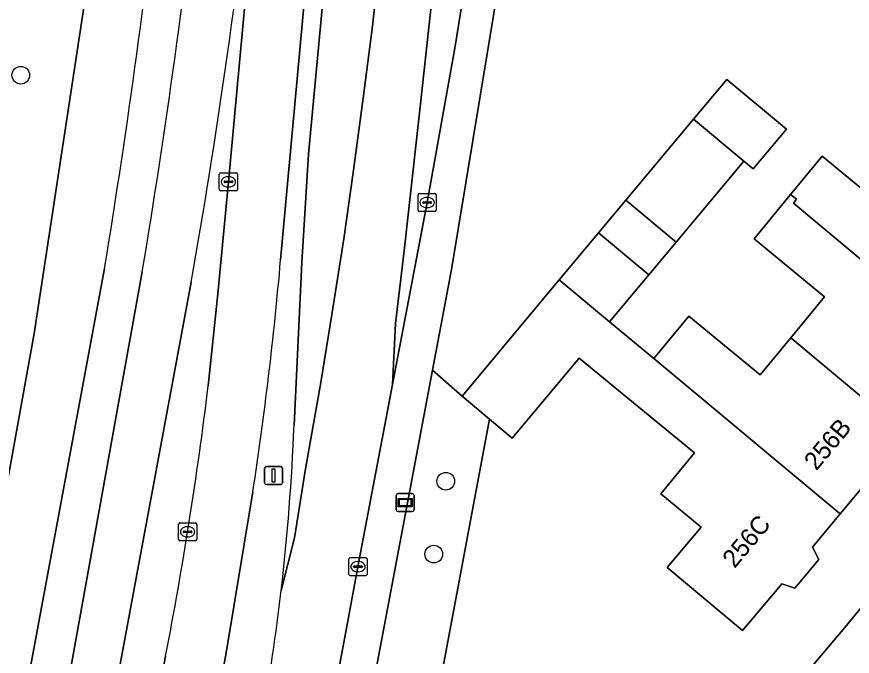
# Model space of a CAD drawing. Extents: x 160157 to 160921, y 381516 to 382045.
# Drawn here: x 160513.39 to 160559.64, y 381764.83 to 381800.21 of the extents above; entities that cross this region are included whole.
import ezdxf

# ---------------------------------------------------------------- set-up
doc = ezdxf.new("R2010")
doc.units = 0
for name, color, linetype in [('IMGEO_Berm_gesloten', 7, 'Continuous'), ('IMGEO_Berm_groen', 7, 'Continuous'), ('IMGEO_Boom', 7, 'Continuous'), ('IMGEO_Erf', 7, 'Continuous'), ('IMGEO_Groenvoorziening', 7, 'Continuous'), ('IMGEO_Kolk', 7, 'Continuous'), ('IMGEO_Lichtmast', 7, 'Continuous'), ('IMGEO_Muur', 7, 'Continuous'), ('IMGEO_Pand', 7, 'Continuous'), ('IMGEO_Pand_nummerreeks', 7, 'Continuous'), ('IMGEO_Rijbaan_regionaal_gesloten', 7, 'Continuous'), ('IMGEO_Voetpad_open', 7, 'Continuous'), ('IMGEO_Wegwijzer', 7, 'Continuous')]:
    doc.layers.add(name, color=color, linetype=linetype)

msp = doc.modelspace()

# ---------------------------------------------------------------- linework, layer by layer
at = {"layer": 'IMGEO_Berm_gesloten'}
for points in [[(160537.367, 381907.526), (160535.336, 381877.881), (160533.178, 381846.489), (160532.157, 381832.058), (160528.001, 381786.763)], [(160528.742, 381777.62), (160529.18, 381786.609), (160529.545, 381792.616), (160532.528, 381824.512), (160533.226, 381832.551), (160534.083, 381843.54), (160536.45, 381877.717), (160538.181, 381902.406)], [(160526.466, 381773.924), (160524.967, 381764.913), (160522.088, 381750), (160521.362, 381746.238)]]:
    msp.add_lwpolyline(points, dxfattribs=at)
for centre, radius, start, end in [((160328.232, 381804.136), 200.523, 351.33458, 355.02985), ((160410.748, 381782.193), 118.083, 353.32437, 357.78058), ((160412.245, 381781.977), 116.571, 350.98273, 353.34405)]:
    msp.add_arc(centre, radius, start, end, dxfattribs=at)
at = {"layer": 'IMGEO_Berm_groen'}
for points in [[(160534.614, 381926.093), (160532.965, 381928.317), (160530.336, 381929.12), (160526.984, 381926.458), (160523.346, 381875.055), (160520.714, 381837.873), (160520.28, 381829.952), (160520.063, 381825.981), (160517.843, 381805.586), (160514.368, 381782.689), (160510.053, 381758.978), (160509.927, 381757.953), (160509.344, 381753.204), (160510.68, 381750.562), (160513.728, 381750), (160514.409, 381749.874), (160514.559, 381750), (160516.8, 381751.896), (160523.052, 381785.526)], [(160523.992, 381779.798), (160524.523, 381784.877), (160525.11, 381791.078), (160526.59, 381807.082), (160527.114, 381812.495), (160528.774, 381830.898), (160530.173, 381850.327), (160531.52, 381869.788), (160533, 381891.221)], [(160505.903, 381781.897), (160505.796, 381779.917), (160504.746, 381758.207), (160509.927, 381757.953), (160510.053, 381758.978), (160514.368, 381782.689), (160517.843, 381805.586)], [(160520.343, 381786.102), (160514.475, 381753.541), (160513.2, 381753.054), (160512.205, 381753.816), (160518.254, 381786.275)], [(160518.254, 381786.275), (160512.205, 381753.816), (160513.2, 381753.054), (160514.475, 381753.541), (160520.343, 381786.102)], [(160523.052, 381785.526), (160516.8, 381751.896), (160514.559, 381750), (160514.409, 381749.874), (160518.635, 381749.141), (160518.807, 381750), (160519.13, 381751.61), (160521.633, 381764.829)]]:
    msp.add_lwpolyline(points, dxfattribs=at)
for centre, radius, start, end in [((160092.55, 381856.358), 431.434, 350.65138, 357.02816), ((160092.55, 381856.358), 431.434, 350.65138, 357.02816), ((160083.837, 381858.802), 442.519, 350.5442, 356.78225), ((160083.837, 381858.802), 442.519, 350.5442, 356.78225), ((160153.748, 381850.796), 375.027, 349.97715, 357.39851), ((160153.748, 381850.796), 375.027, 349.97715, 357.39851), ((160314.708, 381805.109), 210.809, 348.98452, 353.10404)]:
    msp.add_arc(centre, radius, start, end, dxfattribs=at)
at = {"layer": 'IMGEO_Boom'}
for centre in [(160513.621, 381796.978), (160537.142, 381774.514), (160536.478, 381770.482)]:
    msp.add_circle(centre, 0.489, dxfattribs=at)
at = {"layer": 'IMGEO_Erf'}
for points in [[(160540.802, 381806.439), (160539.434, 381798.152), (160537.466, 381786.23), (160536.414, 381780.659), (160538.044, 381779.218), (160543.426, 381785.657), (160545.598, 381788.256), (160547.107, 381790.062), (160550.859, 381794.551), (160552.693, 381796.747), (160555.991, 381793.99), (160554.156, 381791.795), (160553.637, 381792.229), (160549.884, 381787.74), (160548.375, 381785.935), (160546.207, 381783.342), (160548.665, 381781.296), (160550.599, 381783.648), (160554.551, 381780.398), (160556.234, 381782.446), (160558.103, 381784.719), (160554.204, 381787.925), (160556.228, 381790.387), (160557.966, 381792.501), (160561.933, 381789.24)], [(160562.638, 381777.096), (160558.979, 381772.71), (160557.434, 381770.858), (160557.796, 381770.185), (160556.453, 381768.597), (160555.742, 381768.829), (160555.484, 381768.52), (160553.562, 381766.248), (160549.402, 381769.734), (160551.278, 381771.979), (160549.047, 381773.813), (160550.909, 381776.077), (160547.01, 381779.283), (160544.524, 381781.328), (160540.815, 381776.891), (160539.559, 381777.945), (160536.769, 381763.076)], [(160556.812, 381763.555), (160559.232, 381766.417), (160566.256, 381774.976)]]:
    msp.add_lwpolyline(points, dxfattribs=at)
at = {"layer": 'IMGEO_Groenvoorziening'}
msp.add_lwpolyline([(160537.22, 381749.558), (160534.647, 381751.702), (160535.455, 381756.063), (160536.769, 381763.076), (160539.559, 381777.945), (160538.044, 381779.218), (160536.414, 381780.659), (160535.155, 381773.997), (160533.001, 381762.573), (160531.549, 381754.827), (160530.76, 381750.659), (160530.838, 381750)], dxfattribs=at)
at = {"layer": 'IMGEO_Kolk'}
for p, q in [((160524.608, 381790.652), (160524.608, 381791.504)), ((160524.683, 381791.578), (160525.535, 381791.578)), ((160525.609, 381791.504), (160525.609, 381790.652)), ((160524.867, 381791.072), (160524.867, 381791.084)), ((160525.305, 381791.035), (160524.907, 381791.035)), ((160524.91, 381791.121), (160525.308, 381791.121)), ((160525.096, 381791.358), (160525.121, 381791.358)), ((160525.351, 381791.084), (160525.351, 381791.072)), ((160525.535, 381790.578), (160524.683, 381790.578)), ((160525.119, 381790.798), (160525.094, 381790.798)), ((160535.608, 381789.509), (160535.608, 381790.361)), ((160535.683, 381790.435), (160536.535, 381790.435)), ((160536.096, 381790.215), (160536.121, 381790.215)), ((160536.609, 381790.361), (160536.609, 381789.509)), ((160535.867, 381789.929), (160535.867, 381789.941)), ((160536.305, 381789.892), (160535.907, 381789.892)), ((160535.91, 381789.978), (160536.308, 381789.978)), ((160536.119, 381789.655), (160536.094, 381789.655)), ((160536.351, 381789.941), (160536.351, 381789.929)), ((160536.535, 381789.435), (160535.683, 381789.435)), ((160522.353, 381771.29), (160522.353, 381772.142)), ((160522.428, 381772.216), (160523.28, 381772.216)), ((160522.841, 381771.996), (160522.866, 381771.996)), ((160523.354, 381772.142), (160523.354, 381771.29)), ((160522.612, 381771.71), (160522.612, 381771.722)), ((160523.05, 381771.673), (160522.652, 381771.673)), ((160522.655, 381771.759), (160523.053, 381771.759)), ((160523.096, 381771.722), (160523.096, 381771.71)), ((160523.28, 381771.216), (160522.428, 381771.216)), ((160522.864, 381771.436), (160522.839, 381771.436)), ((160531.782, 381769.361), (160531.782, 381770.213)), ((160531.857, 381770.287), (160532.709, 381770.287)), ((160532.783, 381770.213), (160532.783, 381769.361)), ((160532.041, 381769.781), (160532.041, 381769.793)), ((160532.479, 381769.744), (160532.081, 381769.744)), ((160532.084, 381769.83), (160532.482, 381769.83)), ((160532.27, 381770.067), (160532.295, 381770.067)), ((160532.525, 381769.793), (160532.525, 381769.781)), ((160532.709, 381769.287), (160531.857, 381769.287)), ((160532.293, 381769.507), (160532.268, 381769.507))]:
    msp.add_line(p, q, dxfattribs=at)
for points in [[(160524.608, 381790.652), (160524.608, 381791.504)], [(160524.683, 381791.578), (160525.535, 381791.578)], [(160525.609, 381791.504), (160525.609, 381790.652)], [(160525.535, 381790.578), (160524.683, 381790.578)], [(160535.608, 381789.509), (160535.608, 381790.361)], [(160535.683, 381790.435), (160536.535, 381790.435)], [(160536.609, 381790.361), (160536.609, 381789.509)], [(160536.535, 381789.435), (160535.683, 381789.435)], [(160522.353, 381771.29), (160522.353, 381772.142)], [(160522.428, 381772.216), (160523.28, 381772.216)], [(160523.354, 381772.142), (160523.354, 381771.29)], [(160523.28, 381771.216), (160522.428, 381771.216)], [(160531.782, 381769.361), (160531.782, 381770.213)], [(160531.857, 381770.287), (160532.709, 381770.287)], [(160532.783, 381770.213), (160532.783, 381769.361)], [(160532.709, 381769.287), (160531.857, 381769.287)]]:
    msp.add_lwpolyline(points, dxfattribs=at)
for centre, radius, start, end in [((160524.685, 381791.502), 0.0765, 91.552, 178.448), ((160524.685, 381791.502), 0.0765, 91.552, 178.448), ((160525.533, 381791.502), 0.0765, 1.552, 88.448), ((160525.533, 381791.502), 0.0765, 1.552, 88.448), ((160524.907, 381791.081), 0.0403, 85.8775, 175.7526), ((160524.904, 381791.071), 0.0366, 178.938, 274.7102), ((160525.308, 381791.078), 0.043, 264.8664, 352.4533), ((160525.312, 381791.083), 0.0386, 1.7309, 96.639), ((160524.685, 381790.654), 0.0765, 181.552, 268.448), ((160524.685, 381790.654), 0.0765, 181.552, 268.448), ((160525.533, 381790.654), 0.0765, 271.552, 358.448), ((160525.533, 381790.654), 0.0765, 271.552, 358.448), ((160535.685, 381790.359), 0.0765, 91.552, 178.448), ((160535.685, 381790.359), 0.0765, 91.552, 178.448), ((160536.533, 381790.359), 0.0765, 1.552, 88.448), ((160536.533, 381790.359), 0.0765, 1.552, 88.448), ((160535.907, 381789.938), 0.0403, 85.8775, 175.7526), ((160535.904, 381789.928), 0.0366, 178.938, 274.7102), ((160536.308, 381789.935), 0.043, 264.8664, 352.4533), ((160536.312, 381789.94), 0.0386, 1.7309, 96.639), ((160535.685, 381789.511), 0.0765, 181.552, 268.448), ((160535.685, 381789.511), 0.0765, 181.552, 268.448), ((160536.533, 381789.511), 0.0765, 271.552, 358.448), ((160536.533, 381789.511), 0.0765, 271.552, 358.448), ((160522.43, 381772.14), 0.0765, 91.552, 178.448), ((160522.43, 381772.14), 0.0765, 91.552, 178.448), ((160523.278, 381772.14), 0.0765, 1.552, 88.448), ((160523.278, 381772.14), 0.0765, 1.552, 88.448), ((160522.652, 381771.719), 0.0403, 85.8775, 175.7526), ((160522.649, 381771.709), 0.0366, 178.938, 274.7102), ((160523.053, 381771.716), 0.043, 264.8664, 352.4533), ((160523.057, 381771.721), 0.0386, 1.7309, 96.639), ((160522.43, 381771.292), 0.0765, 181.552, 268.448), ((160522.43, 381771.292), 0.0765, 181.552, 268.448), ((160523.278, 381771.292), 0.0765, 271.552, 358.448), ((160523.278, 381771.292), 0.0765, 271.552, 358.448), ((160531.859, 381770.211), 0.0765, 91.552, 178.448), ((160531.859, 381770.211), 0.0765, 91.552, 178.448), ((160532.707, 381770.211), 0.0765, 1.552, 88.448), ((160532.707, 381770.211), 0.0765, 1.552, 88.448), ((160532.081, 381769.79), 0.0403, 85.8775, 175.7526), ((160532.078, 381769.78), 0.0366, 178.938, 274.7102), ((160532.482, 381769.787), 0.043, 264.8664, 352.4533), ((160532.486, 381769.792), 0.0386, 1.7309, 96.639), ((160531.859, 381769.363), 0.0765, 181.552, 268.448), ((160531.859, 381769.363), 0.0765, 181.552, 268.448), ((160532.707, 381769.363), 0.0765, 271.552, 358.448), ((160532.707, 381769.363), 0.0765, 271.552, 358.448)]:
    msp.add_arc(centre, radius, start, end, dxfattribs=at)
for centre, major_axis, ratio, start_param, end_param in [((160525.095, 381791.078), (-0.387, 0.002), 0.722429, 4.712389, 7.853982), ((160525.12, 381791.078), (-0.39, 0.002), 0.717154, 1.570796, 4.712389), ((160536.095, 381789.935), (-0.387, 0.002), 0.722429, 4.712389, 7.853982), ((160536.12, 381789.935), (-0.39, 0.002), 0.717154, 1.570796, 4.712389), ((160522.84, 381771.716), (-0.387, 0.002), 0.722429, 4.712389, 7.853982), ((160522.865, 381771.716), (-0.39, 0.002), 0.717154, 1.570796, 4.712389), ((160532.269, 381769.787), (-0.387, 0.002), 0.722429, 4.712389, 7.853982), ((160532.294, 381769.787), (-0.39, 0.002), 0.717154, 1.570796, 4.712389)]:
    msp.add_ellipse(centre, major_axis=major_axis, ratio=ratio, start_param=start_param, end_param=end_param, dxfattribs=at)
at = {"layer": 'IMGEO_Lichtmast'}
for p, q in [((160527.115, 381774.43), (160527.115, 381775.23)), ((160527.115, 381775.23), (160527.115, 381774.43)), ((160527.215, 381775.33), (160528.005, 381775.33)), ((160528.005, 381775.33), (160527.215, 381775.33)), ((160528.105, 381775.23), (160528.105, 381774.43)), ((160528.105, 381774.43), (160528.105, 381775.23)), ((160528.005, 381774.33), (160527.215, 381774.33)), ((160527.215, 381774.33), (160528.005, 381774.33))]:
    msp.add_line(p, q, dxfattribs=at)
msp.add_lwpolyline([(160527.535, 381775.205), (160527.685, 381775.205), (160527.685, 381774.455), (160527.535, 381774.455), (160527.535, 381775.205)], dxfattribs=at)
for centre, start, end in [((160527.215, 381775.23), 90, 180), ((160527.215, 381775.23), 90, 180), ((160528.005, 381775.23), 0, 90), ((160528.005, 381775.23), 360, 90), ((160527.215, 381774.43), 180, 270), ((160527.215, 381774.43), 180, 270), ((160528.005, 381774.43), 270, 0), ((160528.005, 381774.43), 270, 0)]:
    msp.add_arc(centre, 0.1, start, end, dxfattribs=at)
at = {"layer": 'IMGEO_Muur'}
msp.add_lwpolyline([(160539.559, 381777.945), (160536.769, 381763.076)], dxfattribs=at)
at = {"layer": 'IMGEO_Pand'}
for points in [[(160550.859, 381794.551), (160553.637, 381792.229), (160554.156, 381791.795), (160555.991, 381793.99), (160552.693, 381796.747)], [(160553.637, 381792.229), (160550.859, 381794.551), (160547.107, 381790.062), (160549.884, 381787.74)], [(160566.367, 381781.567), (160569.786, 381785.666), (160565.952, 381788.876), (160563.395, 381791.018), (160561.933, 381789.24), (160557.966, 381792.501), (160556.228, 381790.387), (160556.558, 381790.111), (160556.386, 381789.906)], [(160547.107, 381790.062), (160545.598, 381788.256), (160548.375, 381785.935), (160549.884, 381787.74)], [(160566.367, 381781.567), (160556.386, 381789.906), (160556.558, 381790.111), (160556.228, 381790.387), (160554.204, 381787.925), (160558.103, 381784.719), (160556.234, 381782.446), (160562.638, 381777.096)], [(160543.426, 381785.657), (160546.207, 381783.342), (160548.375, 381785.935), (160545.598, 381788.256)], [(160548.665, 381781.296), (160546.207, 381783.342), (160543.426, 381785.657), (160538.044, 381779.218), (160539.559, 381777.945), (160540.815, 381776.891), (160544.524, 381781.328), (160547.01, 381779.283), (160550.909, 381776.077), (160549.047, 381773.813), (160551.278, 381771.979), (160549.402, 381769.734), (160553.562, 381766.248), (160555.484, 381768.52), (160555.742, 381768.829), (160556.453, 381768.597), (160557.796, 381770.185), (160557.434, 381770.858), (160558.979, 381772.71)], [(160548.665, 381781.296), (160558.979, 381772.71), (160562.638, 381777.096), (160556.234, 381782.446), (160554.551, 381780.398), (160550.599, 381783.648)]]:
    msp.add_lwpolyline(points, close=True, dxfattribs=at)
at = {"layer": 'IMGEO_Rijbaan_regionaal_gesloten'}
for points in [[(160534.257, 381910.641), (160533, 381891.221), (160531.52, 381869.788), (160530.173, 381850.327), (160528.774, 381830.898), (160527.114, 381812.495), (160526.59, 381807.082), (160525.11, 381791.078), (160524.523, 381784.877), (160523.992, 381779.798)], [(160528.001, 381786.763), (160532.157, 381832.058), (160533.178, 381846.489), (160535.336, 381877.881), (160537.367, 381907.526)], [(160538.181, 381902.406), (160536.45, 381877.717), (160534.083, 381843.54), (160533.226, 381832.551), (160532.528, 381824.512), (160529.545, 381792.616), (160529.18, 381786.609), (160528.742, 381777.62)], [(160536.596, 381803.188), (160535.72, 381795.222), (160534.845, 381787.255), (160534.361, 381783.239), (160534.195, 381779.861), (160536.108, 381789.935), (160537.65, 381798.47), (160538.964, 381806.709)], [(160533.505, 381803.628), (160533.081, 381799.699), (160532.56, 381795.716), (160532.039, 381791.732), (160531.492, 381787.917), (160530.846, 381783.843), (160530.233, 381779.971), (160529.38, 381775.201), (160528.772, 381771.385), (160528.03, 381768.466)], [(160528.03, 381768.466), (160528.772, 381771.385), (160529.38, 381775.201), (160530.233, 381779.971), (160530.846, 381783.843), (160531.492, 381787.917), (160532.039, 381791.732), (160532.56, 381795.716), (160533.081, 381799.699), (160533.505, 381803.628)], [(160528.299, 381748.554), (160528.561, 381750), (160529.214, 381753.603), (160531.031, 381763.137), (160531.658, 381766.473), (160532.282, 381769.787), (160534.195, 381779.861), (160534.361, 381783.239), (160534.845, 381787.255), (160535.72, 381795.222), (160536.596, 381803.188)], [(160521.362, 381746.238), (160522.088, 381750), (160524.967, 381764.913), (160526.466, 381773.924)], [(160521.633, 381764.829), (160519.13, 381751.61), (160518.807, 381750), (160518.635, 381749.141), (160518.486, 381748.395)]]:
    msp.add_lwpolyline(points, dxfattribs=at)
for centre, radius, start, end in [((160328.232, 381804.136), 200.523, 351.33458, 355.02985), ((160314.708, 381805.109), 210.809, 348.98452, 353.10404), ((160410.748, 381782.193), 118.083, 353.32437, 357.78058), ((160412.245, 381781.977), 116.571, 350.98273, 353.34405)]:
    msp.add_arc(centre, radius, start, end, dxfattribs=at)
at = {"layer": 'IMGEO_Voetpad_open'}
for points in [[(160536.414, 381780.659), (160537.466, 381786.23), (160539.434, 381798.152), (160540.802, 381806.439), (160543.619, 381823.508), (160543.837, 381826.73)], [(160540.822, 381821.339), (160539.588, 381811.172), (160538.964, 381806.709), (160537.65, 381798.47), (160536.108, 381789.935), (160534.195, 381779.861), (160532.282, 381769.787), (160531.658, 381766.473), (160531.031, 381763.137), (160529.214, 381753.603), (160528.561, 381750), (160528.299, 381748.554)], [(160587.941, 381807.827), (160580.593, 381798.887), (160569.786, 381785.666), (160572.924, 381783.093), (160566.256, 381774.976), (160559.232, 381766.417), (160556.812, 381763.555), (160556.143, 381762.763), (160552.4, 381758.139), (160548.643, 381753.199), (160547.737, 381752.007), (160547.187, 381751.244)], [(160530.838, 381750), (160530.76, 381750.659), (160531.549, 381754.827), (160533.001, 381762.573), (160535.155, 381773.997), (160536.414, 381780.659)]]:
    msp.add_lwpolyline(points, dxfattribs=at)
at = {"layer": 'IMGEO_Wegwijzer'}
for p, q in [((160534.397, 381772.932), (160534.397, 381773.732)), ((160534.397, 381773.732), (160534.397, 381772.932)), ((160534.497, 381773.832), (160535.287, 381773.832)), ((160535.287, 381773.832), (160534.497, 381773.832)), ((160535.387, 381773.732), (160535.387, 381772.932)), ((160535.387, 381772.932), (160535.387, 381773.732)), ((160535.287, 381772.832), (160534.497, 381772.832)), ((160534.497, 381772.832), (160535.287, 381772.832))]:
    msp.add_line(p, q, dxfattribs=at)
for points in [[(160534.498, 381773.564), (160535.286, 381773.564), (160535.286, 381773.1), (160534.498, 381773.1), (160534.498, 381773.564)], [(160534.563, 381773.499), (160534.563, 381773.165), (160535.221, 381773.165), (160535.221, 381773.499), (160534.563, 381773.499)]]:
    msp.add_lwpolyline(points, dxfattribs=at)
for centre, start, end in [((160534.497, 381773.732), 90, 180), ((160534.497, 381773.732), 90, 180), ((160535.287, 381773.732), 0, 90), ((160535.287, 381773.732), 360, 90), ((160534.497, 381772.932), 180, 270), ((160534.497, 381772.932), 180, 270), ((160535.287, 381772.932), 270, 0), ((160535.287, 381772.932), 270, 0)]:
    msp.add_arc(centre, 0.1, start, end, dxfattribs=at)

# ---------------------------------------------------------------- texts
at = {"layer": 'IMGEO_Pand_nummerreeks'}
for s, rotation, p in [('256B', 50.1675, (160557.651, 381775.053)), ('256C', 50.0274, (160553.129, 381769.655))]:
    msp.add_text(s, height=1, rotation=rotation, dxfattribs=at).set_placement(p)

doc.saveas('drawing.dxf')
